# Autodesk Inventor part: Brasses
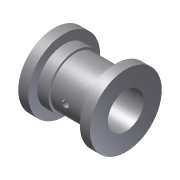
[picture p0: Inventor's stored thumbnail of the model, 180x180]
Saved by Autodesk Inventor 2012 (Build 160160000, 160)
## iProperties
Created: 2009-04
Part Number: Brasses
Document SubType Name: Modeling
Designer: Sham
Density: 1 g/cm^3
Material: Default
Author: Sham
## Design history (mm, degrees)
sketch "Sketch1"
  geometry: L1 (0, 32)-(9, 32); L2 (0, 16)-(64, 16); L3 (64, 32)-(55, 32); L4 (55, 32)-(55, 24); L5 (55, 24)-(47, 24); L6 (19, 22)-(47, 22); L7 (47, 24)-(47, 22); L8 (19, 22)-(19, 24); L9 (19, 24)-(9, 24); L10 (9, 24)-(9, 32); L11 (0, 32)-(0, 16); L12 (64, 32)-(64, 16); L13 (-12.8, 0)-(76.8, 0) reference; 1 further point
  constraints: 24 end point, 7 parallel, 4 perpendicular, 1 collinear, 1 horizontal, 1 vertical alignment, 1 other
  dimensions: "d0" = 9 distance of L1.start L1.end; "d2" = 16 distance from line of L2 point (0, 0); "d3" = 64 distance of L2.start L2.end; "d4" = 24 distance from line of point (0, 0) L5; "d5" = 28 distance of L6.start L6.end; "d6" = 22 distance from line of point (0, 0) L6; "d7" = 8 distance of L4.end L5.end
revolve "Revolution1" sketch "Sketch1" stored, may be unused: angle "d8" = 90 deg
workplane "Work Plane1"
sketch "Sketch2"
  geometry: C1 r 4 at (-32, 0)
  constraints: 1 centre point
  dimensions: "d10" = 8 diameter of C1
extrude "Extrusion1" join sketch "Sketch2" stored distance "d11" = 10; taper "d12" = 0 deg
sketch "Sketch3"
  geometry: C1 r 4 at (0, 0) reference; C2 r 3 at (0, 0)
  constraints: 1 centre point, 1 coincident
  dimensions: "d13" = 6 diameter of C2
extrude "Extrusion2" cut sketch "Sketch3" stored distance "d14" = 10; taper "d15" = 0 deg
body "Solid1"
